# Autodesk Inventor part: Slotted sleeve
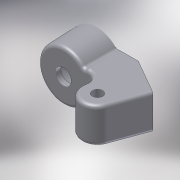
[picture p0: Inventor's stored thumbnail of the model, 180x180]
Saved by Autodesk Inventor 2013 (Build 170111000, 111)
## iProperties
Shininess: 25.0
Length Units: 11269
Angle Units: 11279
Time Units: 11290
Mass Units: 11283
Length Display Precision: 3
Angle Display Precision: 2
Created: 2002-03
Part Number: Slotted sleeve
Material: Steel, Mild
Document SubType Name: Modeling
Designer: =<Author>
Density: 7.86 g/cm^3
Description: =<Part Number>
Density: 7.859999999999999
Volumn: 20.55704884452463
Area: 68.53766832085616
PropertySet Name: Model Information
Control State: 0
Master: False
Checked Out: True
Last Check In Date: 2008-10-15
Checked Out Date: 2008-10-15
Author: LAlexey
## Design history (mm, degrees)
sketch "Sketch1"
  geometry: L1 (-20.851, 23.016)-(-10.069, 23.016); L2 (-10.069, 23.016)-(9.602, 11.659); L3 (9.602, 11.659)-(2.606, -7.562); L4 (-20.851, 23.016)-(-20.851, 4.016); L5 (-20.851, 4.016)-(-19.816, 4.016); C1 r 3 at (-5.851, -4.484); A1 r 5.322 centre (-19.816, -1.306) between (-14.627, -2.487) and (-19.816, 4.016); A2 r 9 centre (-5.851, -4.484) between (-14.627, -2.487) and (2.606, -7.562)
  constraints: 10 end point, 4 point on circle, 3 centre point, 3 tangent, 2 perpendicular, 1 coincident, 1 horizontal
  dimensions: "d0" = 19 distance between parallel lines of L1 L5; "d1" = 9 radius of A2; "d2" = 30 deg angle of L1 L2; "d3" = 100 deg angle of L2 L3; "d4" = 8.5 distance from line of A2.centre L5; "d5" = 15 distance from line of L4 A2.centre; "d6" = 6 diameter of C1
extrude "Extrusion1" new body sketch "Sketch1" distance "d7" = 20; taper "d8" = 0 deg
workaxis "Work Axis1"
sketch "Sketch2"
  geometry: L1 (0, 0)-(10.782, 0) reference; L2 (15, 11)-(15, -31) reference; C1 r 15 at (-13, -10)
  constraints: 1 centre point
  dimensions: "d9" = 30 diameter of C1; "d10" = 28 distance from line of L2 C1.centre; "d11" = 10 distance from line of L1 C1.centre
extrude "Extrusion2" join sketch "Sketch2" distance "d12" = 19; taper "d13" = -2 deg
fillet "Fillet1" dims "d14" = 2
fillet "Fillet2" dims "d15" = 2
fillet "Fillet3" dims "d16" = 2
sketch "Sketch3"
  geometry: C1 r 10 at (-23.782, 10); A1 r 15 centre (-23.782, 10) between (-13.014, 20.443) and (-13.014, -0.443) reference
  constraints: 1 centre point, 1 coincident
  dimensions: "d17" = 20 diameter of C1
extrude "Extrusion3" cut sketch "Sketch3" distance "d18" = 16; taper "d19" = -2 deg
sketch "Sketch4"
  geometry: C1 r 4.5 at (-14.035, 10); A1 r 14.337 centre (-14.035, 10) between (-3.822, 20.061) and (-3.822, -0.061) reference
  constraints: 1 centre point, 1 concentric
  dimensions: "d20" = 9 diameter of C1
extrude "Extrusion4" cut sketch "Sketch4" distance "d21" = 16; taper "d22" = 0 deg
fillet "Fillet4" dims "d23" = 2
body "Solid1"
